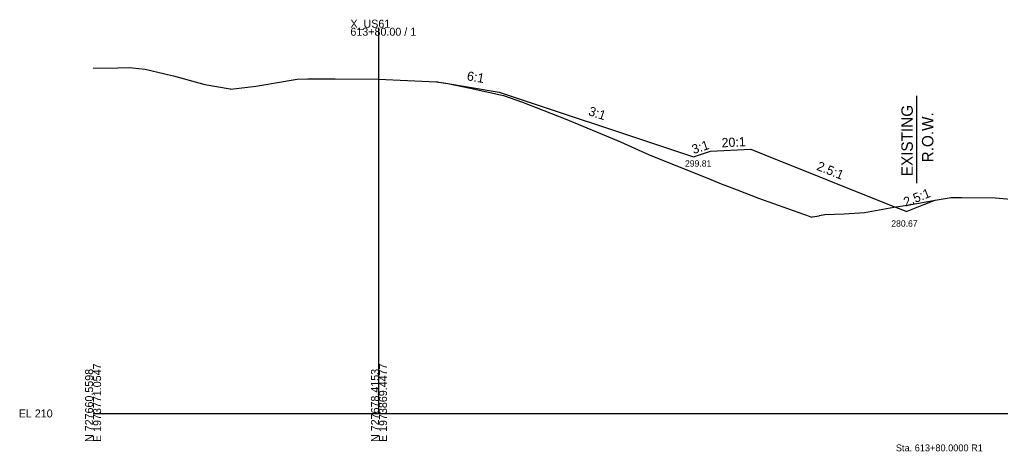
# Model space of a CAD drawing. Extents: x -26 to 1604, y -13 to 9623.
# Drawn here: x -25.7 to 317.3, y 4486.7 to 4637.8 of the extents above; entities that cross this region are included whole.
import ezdxf

# ---------------------------------------------------------------- set-up
doc = ezdxf.new("R2010")
doc.units = 0
for name, color, linetype in [('Draft_XS_Grid', 7, 'Continuous'), ('Draft_XS_Text', 7, 'Continuous'), ('DTM_X_GROUND', 7, 'Continuous'), ('SLOPE_STAKES_FILL', 7, 'Continuous'), ('XS_CELL', 7, 'Continuous'), ('XS_P_GROUND', 7, 'Continuous'), ('XS_P_TX_DCH', 7, 'Continuous'), ('XS_P_TX_FS_BS', 7, 'Continuous'), ('XS_X_ROW', 7, 'Continuous')]:
    doc.layers.add(name, color=color, linetype=linetype)

msp = doc.modelspace()

# ---------------------------------------------------------------- linework, layer by layer
at = {"layer": 'DTM_X_GROUND'}
msp.add_lwpolyline([(0, 4620.86), (8.68, 4621.01), (12.88, 4621.09), (13.77, 4620.98), (18.19, 4620.47), (25.08, 4618.87), (26.06, 4618.64), (28.15, 4618.15), (39.08, 4615.09), (47.96, 4613.6), (48.22, 4613.54), (56.89, 4614.55), (59.67, 4615.02), (63.86, 4615.7), (71.34, 4616.94), (75.08, 4617.12), (75.7, 4617.15), (84.7, 4617.1), (99.85, 4617.02), (120.07, 4616.05), (120.46, 4616.04), (120.86, 4615.98), (124.05, 4615.51), (131.94, 4613.8), (143.59, 4611.3), (150.2, 4608.98), (165.17, 4603.12), (177.47, 4598.03), (184.46, 4595.11), (194.25, 4590.62), (216.07, 4581.85), (220.22, 4580.12), (220.99, 4579.86), (225.27, 4578.22), (232.69, 4575.31), (248.48, 4569.73), (248.82, 4569.62), (249.53, 4569.35), (251.22, 4568.74), (251.48, 4568.79), (253.95, 4569.21), (254.08, 4569.24), (255.91, 4569.62), (262.75, 4569.85), (269.84, 4570.28), (280.04, 4572.14), (284.88, 4572.86), (295.21, 4574.72), (300.08, 4575.6), (303.75, 4575.63), (315.65, 4575.51), (328.79, 4574.26)], dxfattribs=at)
at = {"layer": 'XS_CELL'}
for p, q in [((100, 4500), (100, 4635)), ((0, 4500), (100, 4500)), ((100, 4500), (600, 4500))]:
    msp.add_line(p, q, dxfattribs=at)
at = {"layer": 'XS_P_GROUND'}
for points in [[(122, 4615.81), (142, 4612.48)], [(142, 4612.48), (204, 4591.81), (210, 4589.81), (216, 4591.81), (230, 4592.51), (235, 4590.51)], [(235, 4590.51), (278.6, 4573.07), (284.6, 4570.67)], [(294.33, 4574.56), (294.26, 4574.54), (290.6, 4573.07), (290.45, 4573.01), (284.6, 4570.67)]]:
    msp.add_lwpolyline(points, dxfattribs=at)
at = {"layer": 'XS_X_ROW'}
msp.add_line((288, 4611.18), (288, 4580.63), dxfattribs=at)

# ---------------------------------------------------------------- texts
at = {"layer": 'Draft_XS_Grid'}
msp.add_text('-', height=0.0001, dxfattribs=at).set_placement((0, 4500))
at = {"layer": 'Draft_XS_Text'}
msp.add_text('Sta. 613+80.0000 R1', height=2.4, dxfattribs=at).set_placement((280.78, 4486.75))
at = {"layer": 'SLOPE_STAKES_FILL'}
for p in [(141.96, 4612.42), (203.96, 4591.75), (209.96, 4589.75), (215.96, 4591.75), (229.96, 4592.45), (278.56, 4573.01), (290.56, 4573.01), (294.29, 4574.5), (284.56, 4570.61)]:
    msp.add_text('X', height=0.12, dxfattribs=at).set_placement(p)
at = {"layer": 'XS_CELL'}
for s, p in [('X_US61', (90, 4635)), ('613+80.00 / 1', (90, 4632.2)), ('EL 210', (-26, 4498.6))]:
    msp.add_text(s, height=2.8, dxfattribs=at).set_placement(p)
for s, p in [('N 727660.5598', (0, 4490)), ('E 1973771.0547', (2.8, 4490)), ('N 727678.4153', (100, 4490)), ('E 1973869.4477', (102.8, 4490))]:
    msp.add_text(s, height=2.8, rotation=90, dxfattribs=at).set_placement(p)
at = {"layer": 'XS_P_GROUND'}
for p in [(121.96, 4615.75), (234.96, 4590.45)]:
    msp.add_text('X', height=0.12, dxfattribs=at).set_placement(p)
at = {"layer": 'XS_P_TX_DCH'}
for s, p in [('299.81', (207.03, 4586.36)), ('280.67', (279.18, 4565.35))]:
    msp.add_text(s, height=2.25, dxfattribs=at).set_placement(p)
at = {"layer": 'XS_P_TX_FS_BS'}
for s, rotation, p in [('6:1', 350.5377, (130.59, 4616.62)), ('3:1', 341.5651, (172.99, 4604.49)), ('20:1', 2.8624, (219.91, 4593.12)), ('3:1', 18.4349, (210.04, 4590.75)), ('2.5:1', 338.1986, (252.8, 4585.34)), ('2.5:1', 21.8014, (284.24, 4572.32))]:
    msp.add_text(s, height=3.24, rotation=rotation, dxfattribs=at).set_placement(p)
at = {"layer": 'XS_X_ROW'}
for s, p in [('EXISTING', (286.71, 4583.03)), ('R.O.W.', (293.91, 4587.87))]:
    msp.add_text(s, height=4, rotation=90, dxfattribs=at).set_placement(p)

doc.saveas('drawing.dxf')
